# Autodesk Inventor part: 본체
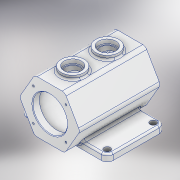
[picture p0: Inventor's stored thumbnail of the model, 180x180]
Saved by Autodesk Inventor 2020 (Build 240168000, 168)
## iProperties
Created: 2021-06
Part Number: 본체
Material: 알루미늄 6061
Document SubType Name: Modeling
Designer: 605-5
Mass: 1495.74 g
Surface Area: 1102.12 cm^2
Volume: 553.978 cm^3
Density: 2.7 g/cm^3
Appearance: 알루미늄 - 평지
Author: 605-5
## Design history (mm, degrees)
sketch "스케치1" dims "d0" = 105
  geometry: L1 (-26.25, 45.466)-(26.25, 45.466); L2 (26.25, 45.466)-(52.5, 0); L3 (52.5, 0)-(26.25, -45.466); L4 (26.25, -45.466)-(-26.25, -45.466); L5 (-26.25, -45.466)-(-52.5, 0); L6 (-52.5, 0)-(-26.25, 45.466); 3 further points
  constraints: 12 end point, 2 coincident, 1 horizontal alignment, 16 other
extrude "돌출1" new body sketch "스케치1" stored distance "d1" = 140; taper "d2" = 0 deg
node "작업 평면1"
sketch "스케치5"
  geometry: L1 (-75, -55)-(75, -55); L2 (75, -55)-(75, 45); L3 (75, 45)-(-75, 45); L4 (-75, 45)-(-75, -55); L5 (52.5, -70)-(26.25, -70) reference; L6 (26.25, 70)-(52.5, 70) reference; 3 further points
  constraints: 8 end point, 2 midpoint, 2 parallel, 1 horizontal, 1 perpendicular, 1 vertical alignment
  dimensions: "d27" = 150 distance between parallel lines of L2 L4; "d28" = 100 distance between parallel lines of L3 L1; "d103" = 25 distance between parallel lines of L3 L6
extrude "돌출4" join sketch "스케치5" distance "d29" = 12; taper "d30" = 0 deg
node "작업 평면2"
sketch "스케치6"
  geometry: L1 (-26.25, 70)-(26.25, 70) reference; C1 r 20 at (0, 30); C2 r 20 at (0, -30); 1 further point
  constraints: 2 centre point, 2 vertical alignment, 1 equal radius
  dimensions: "d32" = 40 diameter of C2; "d33" = 60 distance of C2.centre C1.centre; "d34" = 40 distance from line of C1.centre L1
extrude "돌출5" join sketch "스케치6" stored distance "d35" = 12; taper "d36" = 0 deg
fillet "모깎기2" dims "d37" = 10
sketch "스케치7"
  geometry: A1 r 10 centre (65, 45) between (75, 45) and (65, 55) reference; 2 further points
  constraints: 1 coincident
hole "구멍2" sketch "스케치7" at (65, 45) diameter "d38" = 11; stored, may be unused: countersink angle "d42" = 90 deg, drill point angle "d44" = 118 deg; dims "d39" = 6, "d40" = 4, "d41" = 2, "d43" = 8
sketch "스케치8"
  geometry: L1 (-30.561, 55)-(-65, 55) reference; L2 (-75, 45)-(-75, -35) reference; 2 further points
  constraints: 1 other
  dimensions: "d51" = 50 distance from line of point (-61, 5) L1; "d52" = 14 distance from line of point (-61, 5) L2
feature "엠보싱1" sketch "스케치8" dims "d53" = 0.5, "d54" = 0
sketch "스케치9"
  geometry: L1 (45.466, -70)-(0, -70) reference; L2 (0, 70)-(45.466, 70) reference; L3 (0, -70)-(0, 70) reference; L4 (0, -70)-(0, 70); L5 (30, -70)-(30, -58); L6 (30, -58)-(37.5, -58); L7 (37.5, -58)-(37.5, 58); L8 (37.5, 58)-(30, 58); L9 (30, 58)-(30, 70); 1 further point
  constraints: 12 end point, 3 perpendicular, 2 collinear, 2 point on line, 2 vertical, 1 horizontal
  dimensions: "d55" = 12 distance between parallel lines of L6 L1; "d56" = 75 diameter of L7 L3; "d57" = 60 diameter of L5 L3
revolve "회전1" sketch "스케치9" stored, may be unused: angle "d58" = 90 deg
sketch "스케치10"
  geometry: L1 (-28.284, 28.284)-(0, 0); L2 (0, 0)-(28.284, 28.284); L3 (0, 0)-(0, 40); C1 r 30 at (0, 0) reference; A1 r 40 centre (0, 0) between (-28.284, 28.284) and (28.284, 28.284); 2 further points
  constraints: 6 end point, 3 point on circle, 2 coincident, 1 centre point, 1 vertical
  dimensions: "d59" = 80 diameter of A1; "d60" = 45 deg angle of L3 L1; "d61" = 90 deg angle of L2 L1
hole "구멍3" sketch "스케치10" at (-28.284, 28.284) diameter "d62" = 3.242; stored, may be unused: countersink angle "d66" = 90 deg, drill point angle "d68" = 120 deg; dims "d63" = 8, "d64" = 4, "d65" = 2, "d67" = 10
sketch "스케치11" dims "d72" = 80
  geometry: 3 further points
  constraints: 2 vertical alignment, 1 coincident, 2 other
hole "구멍4" sketch "스케치11" at (0, 40) diameter "d73" = 3.242; stored, may be unused: countersink angle "d77" = 90 deg, drill point angle "d79" = 120 deg; dims "d74" = 8, "d75" = 4, "d76" = 2, "d78" = 10
sketch "스케치12"
  geometry: C1 r 20 at (0, 0) reference; C2 r 20 at (0, 60) reference; 3 further points
  constraints: 2 coincident
hole "구멍5" sketch "스케치12" at (0, 0), (0, 60) diameter "d83" = 25; stored, may be unused: countersink angle "d87" = 90 deg, drill point angle "d89" = 0 deg; dims "d84" = 8, "d85" = 30, "d86" = 8, "d88" = 36.75
fillet "모깎기3" dims "d90" = 5
chamfer "모따기1" distance "d91" = 1; stored, may be unused: second distance "d92" = 2, angle "d93" = 45 deg
fillet "모깎기4" dims "d94" = 8
fillet "모깎기5" dims "d95" = 3
fillet "모깎기9" dims "d99" = 8
fillet "모깎기10" dims "d100" = 3
fillet "모깎기11" dims "d101" = 3
node "솔리드1"
pattern_linear "직사각형 패턴2" dims "d47" = 130, "d50" = 80
pattern_circular "원형 패턴1" dims angle "d70" = 360 deg
pattern_circular "원형 패턴2" dims angle "d81" = 360 deg
feature "A9D066F2-1C7D-4E18-AEED-F7BC21143FA4" dims "d38" = 11, "d39" = 6, "d40" = 4, "d41" = 2, "d42" = 90 deg, "d43" = 8, "d44" = 118 deg
other parameters: "d31" = 52.5
